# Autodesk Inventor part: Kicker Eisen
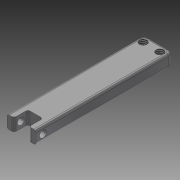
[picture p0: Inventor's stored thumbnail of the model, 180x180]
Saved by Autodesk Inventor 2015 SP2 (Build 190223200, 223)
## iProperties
Created: 2015-08
Part Number: Kicker Eisen
Material: Stahl, galvanisiert
Document SubType Name: Modeling
Designer: rYan
Mass: 30.9042 g
Surface Area: 23.4977 cm^2
Volume: 3.93684 cm^3
Density: 7.85 g/cm^3
Appearance: Galvanisiert
Author: rYan
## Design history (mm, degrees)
sketch "Skizze1"
  geometry: L1 (6.25, 2.75)-(-6.25, 2.75); L2 (-6.25, 2.75)-(-6.25, -2.75); L3 (-6.25, -2.75)-(6.25, -2.75); L4 (6.25, -2.75)-(6.25, 2.75); L5 (0, -3.85)-(0, 3.85) reference; L6 (-8.75, 0)-(8.75, 0) reference; 1 further point
  constraints: 8 end point, 2 parallel, 1 horizontal, 1 perpendicular, 2 other
  dimensions: "d0" = 12.5 distance of L1.start L1.end; "d1" = 5.5 distance of L1.end L2.end
extrude "Extrusion1" new body sketch "Skizze1" distance "d2" = 53; taper "d3" = 0 deg
sketch "Skizze2"
  geometry: L1 (-6.25, 2.75)-(6.25, 2.75) reference; L2 (-6.25, -2.75)-(-6.25, 2.75) reference; L3 (6.25, -2.75)-(-6.25, -2.75) reference; L4 (6.25, 2.75)-(6.25, -2.75) reference; L5 (6.25, -2.75)-(-6.25, -2.75) reference; L6 (-6.25, 2.75)-(-3.25, 2.75); L7 (-3.25, 2.75)-(-3.25, -2.75); L8 (-3.25, -2.75)-(-6.25, -2.75); L9 (-6.25, -2.75)-(-6.25, 2.75); L10 (6.25, 2.75)-(3.25, 2.75); L11 (3.25, 2.75)-(3.25, -2.75); L12 (3.25, -2.75)-(6.25, -2.75); L13 (6.25, -2.75)-(6.25, 2.75); L14 (0, 3.85)-(0, -3.85) reference; 1 further point
  constraints: 16 end point, 4 parallel, 2 horizontal, 2 perpendicular, 2 point on line, 1 other
  dimensions: "d4" = 3 distance between parallel lines of L2 L7
extrude "Extrusion2" join sketch "Skizze2" distance "d5" = 6; taper "d6" = 0 deg
sketch "Skizze3"
  geometry: L1 (5.5, 0)-(5.5, -59) reference; L2 (0, 0)-(5.5, 0) reference; L3 (0, -59)-(0, 0) reference; L4 (5.5, -59)-(0, -59) reference; L5 (5.5, -59)-(5.5, 0) reference; L6 (5.5, -56)-(0, -56); 2 further points
  constraints: 2 end point, 2 point on line, 1 midpoint, 1 perpendicular
  dimensions: "d7" = 3 distance between parallel lines of L6 L4
hole "Verbindungsbolzen" sketch "Skizze3" at (2.75, -56) diameter "d8" = 3; stored, may be unused: countersink angle "d12" = 90 deg, drill point angle "d14" = 118 deg; dims "d9" = 6, "d10" = 4, "d11" = 2, "d13" = 8
sketch "Skizze4"
  geometry: L1 (3, -53)-(9.5, -53) reference; L2 (9.5, -53)-(9.5, -59) reference; L3 (12.5, -59)-(9.5, -59) reference; L4 (12.5, -59)-(12.5, 0) reference; L5 (0, 0)-(12.5, 0) reference; L6 (0, 0)-(0, -59) reference; L7 (3, -59)-(0, -59) reference; L8 (3, -53)-(3, -59) reference; L9 (2.65, -3)-(9.85, -3); L10 (0, 0)-(12.5, 0) reference; L11 (6.25, 0)-(6.25, -53); 2 further points
  constraints: 4 end point, 2 coincident, 1 horizontal, 1 midpoint, 1 symmetric about line, 1 vertical
  dimensions: "d15" = 7.2 distance of L9.start L9.end; "d16" = 3 distance between parallel lines of L5 L9
hole "Stoppschrauben" sketch "Skizze4" at (2.65, -3), (9.85, -3) diameter "d17" = 3.242; stored, may be unused: countersink angle "d21" = 90 deg, drill point angle "d23" = 118 deg; dims "d18" = 8, "d19" = 4, "d20" = 2, "d22" = 11.8
fillet "Rundung1" dims "d24" = 2
fillet "Fillet2" dims "d25" = 1
fillet "Rundung3" dims "d26" = 1
node "Volumenkörper1"
node "Projizierte Kontur1"
node "Projizierte Kontur2"
node "Projizierte Kontur3"
